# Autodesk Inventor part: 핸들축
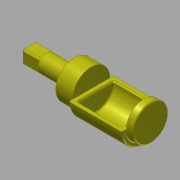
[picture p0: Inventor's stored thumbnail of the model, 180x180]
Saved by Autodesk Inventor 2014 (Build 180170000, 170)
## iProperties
Created: 2018-01
Part Number: 핸들축
Material: 강철, 연강
Document SubType Name: Modeling
Designer: mduedu
Density: 1 g/cm^3
Appearance: Yellow
Author: mduedu
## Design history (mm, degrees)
sketch "스케치1"
  geometry: L1 (0, 0)-(-38, 0); L2 (-38, 0)-(-38, -7.5); L3 (-38, -7.5)-(0, -7.5); L4 (0, -7.5)-(0, 0); L5 (-38, 0)-(-53, 0); L6 (-53, 0)-(-53, -16); L7 (-53, -16)-(-38, -16); L8 (-38, -16)-(-38, 0); L9 (-53, 0)-(-98, 0); L10 (-98, 0)-(-98, -19); L11 (-98, -19)-(-53, -19); L12 (-53, -19)-(-53, 0); L13 (-98, 0)-(-104, 0); L14 (-104, 0)-(-104, -15); L15 (-104, -15)-(-98, -15); L16 (-98, -15)-(-98, 0)
  constraints: 32 end point, 8 parallel, 4 horizontal, 4 perpendicular
  dimensions: "d0" = 6 distance of L14.end L15.end; "d2" = 30 diameter of L15 L13; "d3" = 32 diameter of L7 L5; "d4" = 15 distance of L6.end L7.end; "d5" = 45 distance of L10.end L11.end; "d6" = 38 diameter of L11 L9; "d7" = 38 distance of L2.end L3.end; "d8" = 15 diameter of L3 L1
revolve "회전1" sketch "스케치1" stored, may be unused: angle "d9" = 90 deg
sketch "스케치2"
  geometry: L1 (0, -7.5)-(0, 7.5) reference; L2 (0, 7.5)-(38, 7.5) reference; L3 (38, 7.5)-(38, 16) reference; L4 (38, 16)-(53, 16) reference; L5 (53, 16)-(53, 19) reference; L6 (53, 19)-(98, 19) reference; L7 (98, 19)-(98, 15) reference; L8 (98, 15)-(104, 15) reference; L9 (104, 15)-(104, -15) reference; L10 (104, -15)-(98, -15) reference; L11 (98, -15)-(98, -19) reference; L12 (98, -19)-(53, -19) reference; L13 (53, -19)-(53, -16) reference; L14 (53, -16)-(38, -16) reference; L15 (38, -16)-(38, -7.5) reference; L16 (38, -7.5)-(0, -7.5) reference; L17 (0, 0)-(104, 0); L18 (53, 19)-(53, 0); L19 (98, 19)-(98, 0); L20 (98, 0)-(53, 0); L21 (98, 19)-(53, 19)
  constraints: 10 end point, 3 perpendicular, 2 point on line, 1 midpoint, 1 parallel
extrude "돌출1" cut sketch "스케치2" stored distance "d10" = 10; taper "d11" = 0 deg
sketch "스케치3"
  geometry: L1 (45, 0)-(0, 0) reference; L2 (45, 4)-(45, 0) reference; L3 (45, 34)-(45, 4) reference; L4 (45, 38)-(45, 34) reference; L5 (0, 38)-(45, 38) reference; L6 (0, 35)-(0, 38) reference; L7 (0, 35)-(0, 3) reference; L8 (0, 0)-(0, 3) reference; L9 (0, 19)-(45, 19); L10 (4, 19)-(41, 19); L11 (41, 19)-(41, 34); L12 (41, 34)-(4, 34); L13 (4, 34)-(4, 19); 1 further point
  constraints: 10 end point, 2 midpoint, 2 parallel, 1 horizontal, 1 perpendicular, 1 point on line
  dimensions: "d12" = 4 distance between parallel lines of L3 L11; "d13" = 4 distance between parallel lines of L7 L13; "d14" = 4 distance between parallel lines of L12 L5
revolve "회전2" sketch "스케치3" stored, may be unused: angle "d15" = 90 deg
fillet "모깎기1" dims "d16" = 1
chamfer "모따기1" distance "d17" = 1; stored, may be unused: second distance "d18" = 2, angle "d19" = 45 deg
sketch "스케치4"
  geometry: L1 (-6, -6)-(-4.5, -6); L2 (6, -6)-(6, -4.5); L3 (6, 6)-(4.5, 6); L4 (-6, 6)-(-6, 4.5); L5 (-6, -6)-(6, 6); L6 (6, -6)-(-6, 6); L7 (-4.5, 6)-(-6, 6); L8 (-6, 4.5)-(-6, -4.5); L9 (-6, -4.5)-(-6, -6); L10 (-4.5, -6)-(4.5, -6); L11 (4.5, -6)-(6, -6); L12 (6, -4.5)-(6, 4.5); L13 (6, 4.5)-(6, 6); L14 (4.5, 6)-(-4.5, 6); C1 r 7.5 at (0, 0) reference; 2 further points
  constraints: 28 end point, 18 parallel, 9 perpendicular, 3 horizontal, 2 midpoint, 1 coincident, 11 other
  dimensions: "d20" = 12 distance of L4.start L3.start; "d21" = 12 distance of L3.start L2.start (= d20)
extrude "돌출2" cut sketch "스케치4" distance "d22" = 15; taper "d23" = 0 deg
chamfer "모따기2" distance "d24" = 1; stored, may be unused: second distance "d25" = 2, angle "d26" = 45 deg
sketch "스케치5"
  geometry: 2 further points
  constraints: 1 coincident
hole "구멍1" sketch "스케치5" at (5, 4.153) diameter "d27" = 2.459; stored, may be unused: countersink angle "d31" = 90 deg, drill point angle "d33" = 120 deg; dims "d28" = 6.9, "d29" = 4, "d30" = 2, "d32" = 8.4
node "솔리드1"
node "투영된 루프1"
node "절단 모서리 투영1"
